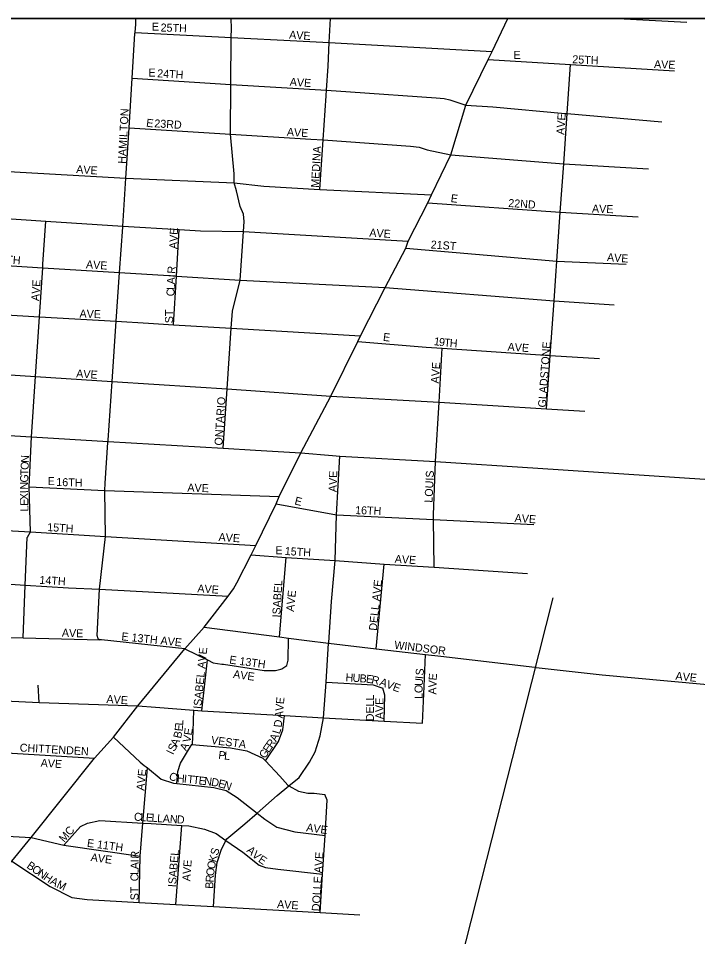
# Model space of a CAD drawing. Extents: x 0 to 34, y -6.2 to 22.
# Drawn here: x 7.668 to 8.471, y 20.104 to 21.19 of the extents above; entities that cross this region are included whole.
import ezdxf

# ---------------------------------------------------------------- set-up
doc = ezdxf.new("R2010")
doc.units = 0
for name, color, linetype in [('GM_X_City_Street', 7, 'Continuous'), ('GM_X_City_Street_Text', 7, 'Continuous'), ('GM_X_Corporation', 7, 'Continuous'), ('GM_X_Rail_Line', 7, 'Continuous'), ('GM_X_State_Route', 7, 'Continuous'), ('GM_X_Township', 7, 'Continuous'), ('SH_Data', 7, 'Continuous')]:
    doc.layers.add(name, color=color, linetype=linetype)

msp = doc.modelspace()

# ---------------------------------------------------------------- linework, layer by layer
at = {"layer": 'GM_X_City_Street'}
for points in [[(7.7742, 20.6887), (7.7743, 20.6898), (7.7744, 20.6915), (7.7792, 20.7608), (7.7841, 20.8319), (7.788, 20.8896), (7.7917, 20.9431), (7.7918, 20.9446), (7.7954, 21.0011), (7.7991, 21.0606), (7.8028, 21.1193), (7.8061, 21.1721), (7.8063, 21.1736), (7.8071, 21.1835), (7.8072, 21.1902)], [(7.9105, 20.6818), (7.9152, 20.7521), (7.92, 20.8236), (7.9214, 20.8438), (7.9306, 20.8806), (7.9343, 20.9383), (7.9351, 20.9498), (7.9346, 20.9585), (7.9306, 20.9676), (7.9262, 20.9863), (7.9233, 20.9957), (7.9233, 21.0062), (7.919, 21.0533), (7.9195, 21.1121), (7.92, 21.1677), (7.9201, 21.1781), (7.9198, 21.1902)], [(8.0321, 21.099), (8.0326, 21.1051), (8.0345, 21.1336), (8.0359, 21.1615), (8.0374, 21.1902)], [(8.3769, 21.1902), (8.4586, 21.1855)], [(7.8063, 21.1736), (7.92, 21.1677), (7.9973, 21.1636), (8.0359, 21.1615), (8.2283, 21.1508)], [(8.2237, 21.1414), (8.3212, 21.1355), (8.4438, 21.128)], [(8.2927, 20.7283), (8.2971, 20.7916), (8.3017, 20.8561), (8.3038, 20.8856), (8.305, 20.9031), (8.309, 20.9608), (8.313, 21.0183), (8.3171, 21.0775), (8.3212, 21.1355)], [(7.8028, 21.1193), (7.9195, 21.1121), (8.0326, 21.1051), (8.061, 21.1033), (8.1621, 21.0963), (8.1715, 21.0955), (8.1783, 21.0937), (8.1892, 21.0903), (8.1973, 21.0877), (8.2292, 21.0856), (8.3147, 21.0777), (8.3171, 21.0775), (8.429, 21.0678)], [(8.0246, 20.9876), (8.0286, 21.0464), (8.0321, 21.0984), (8.0321, 21.099)], [(7.7991, 21.0606), (7.919, 21.0533), (8.014, 21.0475), (8.0286, 21.0464), (8.1318, 21.039), (8.1423, 21.0378), (8.1517, 21.0348), (8.1795, 21.0287), (8.313, 21.0183), (8.4131, 21.0122)], [(7.5578, 21.011), (7.5625, 21.0135), (7.5682, 21.0144), (7.6217, 21.0112), (7.7954, 21.0011), (7.9233, 20.9957), (7.9583, 20.9916), (8.0246, 20.9876), (8.1566, 20.9814)], [(8.1525, 20.9721), (8.309, 20.9608), (8.4012, 20.9554)], [(7.5547, 20.9598), (7.6189, 20.9557), (7.7009, 20.9505), (7.7918, 20.9446), (7.8584, 20.9404), (7.8837, 20.9388), (7.9343, 20.9383), (8.1293, 20.9267)], [(7.6971, 20.8952), (7.6974, 20.8994), (7.7009, 20.9505)], [(7.8517, 20.8278), (7.8551, 20.8854), (7.8584, 20.9404)], [(8.1265, 20.9182), (8.305, 20.9031), (8.387, 20.8994)], [(7.5578, 20.9039), (7.6165, 20.9002), (7.6971, 20.8952), (7.788, 20.8896), (7.846, 20.886), (7.8551, 20.8854), (7.9306, 20.8806), (8.1019, 20.8718), (8.3017, 20.8561), (8.3726, 20.8513)], [(7.679, 20.5766), (7.6825, 20.583), (7.6812, 20.6361), (7.6837, 20.6951), (7.6885, 20.7666), (7.6932, 20.8373), (7.6971, 20.8952)], [(7.5624, 20.8452), (7.6139, 20.8421), (7.6932, 20.8373), (7.7841, 20.8319), (7.8221, 20.8296), (7.8517, 20.8278), (7.92, 20.8236), (8.0729, 20.8148)], [(8.0697, 20.8079), (8.1505, 20.8013), (8.1695, 20.8), (8.2971, 20.7916), (8.3554, 20.7878)], [(8.159, 20.5975), (8.1592, 20.603), (8.1616, 20.6661), (8.1657, 20.7363), (8.1695, 20.8)], [(7.5672, 20.7744), (7.6885, 20.7666), (7.7792, 20.7608), (7.8777, 20.7544), (7.9152, 20.7521), (8.0375, 20.7433), (8.1657, 20.7363), (8.2927, 20.7283), (8.3381, 20.7255)], [(7.6049, 20.7005), (7.6098, 20.6996), (7.6248, 20.6987), (7.6837, 20.6951), (7.7743, 20.6898), (7.9105, 20.6818), (7.9486, 20.6796)], [(7.7667, 20.4551), (7.7647, 20.4553), (7.7632, 20.4561), (7.7625, 20.4565), (7.7614, 20.4603), (7.7643, 20.515), (7.7714, 20.5775), (7.7704, 20.6317), (7.7709, 20.6404), (7.7742, 20.6887)], [(7.9486, 20.6796), (8.0022, 20.6765), (8.0397, 20.6733)], [(8.0352, 20.452), (8.0383, 20.5005), (8.0428, 20.5488), (8.0443, 20.6031), (8.0483, 20.6725)], [(8.0397, 20.6733), (8.0483, 20.6725), (8.1616, 20.6661), (8.2825, 20.6581)], [(8.2825, 20.6581), (8.5455, 20.6407), (8.6, 20.634), (8.6625, 20.6299), (8.7252, 20.6249), (8.7866, 20.6204), (8.8412, 20.6135), (8.9134, 20.612), (8.9666, 20.6077), (8.9733, 20.6073)], [(7.6812, 20.6361), (7.7704, 20.6317), (7.9766, 20.6245)], [(7.9732, 20.6161), (8.0443, 20.6031), (8.159, 20.5975), (8.2778, 20.5917)], [(8.1598, 20.5411), (8.159, 20.5975)], [(7.6256, 20.586), (7.6825, 20.583), (7.7714, 20.5775), (7.9489, 20.5667)], [(7.674, 20.4574), (7.6765, 20.52), (7.6788, 20.5762), (7.679, 20.5766)], [(7.9434, 20.5555), (7.9848, 20.5526), (8.0428, 20.5488), (8.1009, 20.5448), (8.1598, 20.5411), (8.2701, 20.5335)], [(7.977, 20.4589), (7.9848, 20.5526)], [(8.0912, 20.4446), (8.1009, 20.5448)], [(7.611, 20.5242), (7.6765, 20.52), (7.7276, 20.5168), (7.7643, 20.515), (7.9165, 20.507)], [(7.5385, 20.4621), (7.5505, 20.4602), (7.5959, 20.4592), (7.6045, 20.459), (7.674, 20.4574), (7.7647, 20.4553)], [(7.8881, 20.4703), (7.977, 20.4589), (7.9877, 20.4573), (8.0093, 20.4542), (8.0351, 20.4512), (8.0912, 20.4446), (8.1498, 20.4378), (8.1676, 20.4357), (8.2787, 20.4228)], [(7.865, 20.4446), (7.7667, 20.4551)], [(7.8988, 20.1397), (7.9014, 20.177), (7.9033, 20.1918), (7.9079, 20.2065), (7.9137, 20.2179), (7.9147, 20.2199), (7.9361, 20.2376), (7.9505, 20.2502), (7.9742, 20.271), (7.9882, 20.2825), (8.0002, 20.2923), (8.0124, 20.3106), (8.0192, 20.3226), (8.0251, 20.3417), (8.0291, 20.363), (8.0322, 20.4049), (8.0351, 20.4512), (8.0352, 20.452), (8.0352, 20.452)], [(7.9797, 20.421), (7.9857, 20.4249), (7.9874, 20.4313), (7.9877, 20.4573)], [(7.865, 20.4446), (7.8917, 20.4317), (7.8987, 20.4281), (7.9087, 20.4265), (7.9109, 20.4262)], [(7.8853, 20.3713), (7.8917, 20.4317)], [(8.146, 20.3566), (8.148, 20.3998), (8.1498, 20.4378)], [(7.9109, 20.4262), (7.9587, 20.4188), (7.9723, 20.4188), (7.9787, 20.4206), (7.9796, 20.4209), (7.9797, 20.421)], [(8.2787, 20.4228), (8.2804, 20.4226), (8.3584, 20.4136), (8.5171, 20.3992)], [(7.6927, 20.3812), (7.6917, 20.4016)], [(8.0322, 20.4049), (8.0878, 20.4019), (8.0991, 20.3978)], [(8.1009, 20.359), (8.1015, 20.3897), (8.0991, 20.3978)], [(7.5372, 20.3923), (7.5496, 20.3911), (7.5953, 20.3869), (7.62, 20.3846), (7.6927, 20.3812), (7.8095, 20.377), (7.8303, 20.3754)], [(7.8303, 20.3754), (7.8759, 20.3718), (7.8853, 20.3713), (7.9829, 20.3656), (8.0291, 20.363), (8.1009, 20.359), (8.146, 20.3566)], [(7.8557, 20.2851), (7.8567, 20.2994), (7.86, 20.3092), (7.8696, 20.3252), (7.8734, 20.3314), (7.874, 20.3323), (7.8751, 20.3467), (7.8759, 20.3718)], [(7.9604, 20.3119), (7.976, 20.3348), (7.9809, 20.3487), (7.9829, 20.3656)], [(7.7809, 20.34), (7.8121, 20.3104), (7.8171, 20.3067)], [(7.8734, 20.3314), (7.9189, 20.3273), (7.9385, 20.3237), (7.9572, 20.3152), (7.9604, 20.3119), (7.9775, 20.2941), (7.987, 20.2832), (7.9882, 20.2825), (7.9993, 20.276), (8.0106, 20.2738), (8.0178, 20.274), (8.0307, 20.2721)], [(7.5947, 20.324), (7.648, 20.3218), (7.7582, 20.3153)], [(7.811, 20.1445), (7.8122, 20.1993), (7.8155, 20.2383), (7.8211, 20.3036)], [(7.8171, 20.3067), (7.8194, 20.305), (7.8211, 20.3036), (7.8371, 20.2905), (7.8518, 20.2855), (7.8557, 20.2851), (7.8994, 20.2804), (7.9141, 20.2769), (7.9271, 20.2686), (7.9505, 20.2502), (7.9597, 20.243), (7.9739, 20.2335), (7.9953, 20.2279), (8.0309, 20.2236)], [(8.0252, 20.1327), (8.028, 20.178), (8.0309, 20.2236), (8.0335, 20.2656), (8.0307, 20.2721)], [(7.0262, 20.2529), (7.0739, 20.2508), (7.1627, 20.2469), (7.2147, 20.245), (7.2579, 20.2435), (7.3116, 20.2416), (7.3693, 20.2396), (7.3718, 20.2395), (7.4115, 20.2379), (7.4632, 20.2358), (7.5007, 20.2343), (7.5328, 20.2314), (7.5542, 20.2296), (7.5864, 20.2268), (7.6479, 20.2232), (7.6835, 20.2215)], [(7.7221, 20.2125), (7.7419, 20.2343), (7.75, 20.2382), (7.7645, 20.2413), (7.8155, 20.2383), (7.8252, 20.2378)], [(7.8252, 20.2378), (7.8617, 20.2357), (7.8697, 20.2353), (7.8885, 20.2313), (7.902, 20.226), (7.9137, 20.2179), (7.9336, 20.2042), (7.9529, 20.1885), (7.9604, 20.186), (7.9751, 20.1841), (8.028, 20.178)], [(7.8545, 20.1421), (7.8617, 20.2357)], [(7.6835, 20.2215), (7.7221, 20.2125), (7.8122, 20.1993)], [(7.6606, 20.1934), (7.7058, 20.1636), (7.7316, 20.1503), (7.7497, 20.1479), (7.811, 20.1445), (7.8545, 20.1421), (7.8988, 20.1397), (8.0252, 20.1327), (8.0721, 20.1301)]]:
    msp.add_lwpolyline(points, dxfattribs=at)
at = {"layer": 'GM_X_Corporation'}
msp.add_lwpolyline([(5.4833, 14.3902), (9.0755, 14.3902), (9.0755, 21.1902), (4.181, 21.1902)], dxfattribs=at)
at = {"layer": 'GM_X_Rail_Line'}
msp.add_lwpolyline([(8.1767, 20.0174), (8.1914, 20.0742), (8.2588, 20.3396), (8.3007, 20.5048)], dxfattribs=at)
at = {"layer": 'GM_X_State_Route'}
for points in [[(8.0022, 20.6765), (8.0375, 20.7433), (8.0697, 20.8079), (8.0729, 20.8148), (8.1019, 20.8718), (8.1265, 20.9182), (8.1293, 20.9267), (8.1525, 20.9721), (8.1566, 20.9814), (8.1795, 21.0287), (8.1973, 21.0877), (8.2237, 21.1414), (8.2283, 21.1508), (8.2469, 21.1902)], [(7.5487, 20.0559), (7.5562, 20.065), (7.6299, 20.1615), (7.6606, 20.1934), (7.6835, 20.2215), (7.7582, 20.3153), (7.7809, 20.34), (7.8095, 20.377), (7.865, 20.4446), (7.8881, 20.4703), (7.9165, 20.507), (7.9227, 20.5156), (7.9267, 20.5227), (7.9434, 20.5555), (7.9489, 20.5667), (7.9732, 20.6161), (7.9766, 20.6245), (8.0022, 20.6765)]]:
    msp.add_lwpolyline(points, dxfattribs=at)
at = {"layer": 'GM_X_Township'}
msp.add_line((9.0029, 21.1902), (4.1671, 21.1902), dxfattribs=at)
at = {"layer": 'SH_Data'}
msp.add_lwpolyline([(9.0755, 21.1902), (9.0755, 14.3902), (2.2755, 14.3902), (2.2755, 21.1902)], close=True, dxfattribs=at)

# ---------------------------------------------------------------- texts
at = {"layer": 'GM_X_City_Street_Text'}
for s, rotation, p in [('E', 0, (7.8262, 21.1756)), ('25TH', 358.2109, (7.8363, 21.1747)), ('A', 355.0766, (7.9881, 21.1664)), ('V', 356.3898, (7.9966, 21.1657)), ('E', 356.7969, (8.005, 21.1651)), ('E', 0, (8.2537, 21.1422)), ('25TH', 357.2752, (8.323, 21.1372)), ('AVE', 358.0264, (8.4196, 21.1314)), ('E', 0, (7.8221, 21.1214)), ('24TH', 356.4254, (7.8322, 21.1206)), ('AVE', 356.0494, (7.9889, 21.1106)), ('HAMILTON', 86.9077, (7.7953, 21.018)), ('E', 352.8783, (7.819, 21.0622)), ('23RD', 356.5338, (7.8288, 21.0614)), ('AVE', 86.0494, (8.3136, 21.0522)), ('AVE', 356.0499, (7.9855, 21.0514)), ('MEDINA', 86.9313, (8.0236, 20.9897)), ('AVE', 356.0569, (7.7364, 21.0072)), ('E', 352.8783, (8.179, 20.973)), ('22ND', 356.1015, (8.2472, 20.9672)), ('AVE', 358.0261, (8.3463, 20.9606)), ('AVE', 87.9557, (7.8561, 20.9172)), ('AVE', 356.0569, (8.083, 20.9322)), ('21ST', 356.1879, (8.1555, 20.9181)), ('20TH', 355.9114, (7.6397, 20.9014)), ('AVE', 355.9166, (8.3639, 20.9031)), ('AVE', 356.0569, (7.748, 20.8947)), ('R', 85.795, (7.8538, 20.8879)), ('I', 86.7208, (7.8536, 20.8838)), ('AVE', 86.0569, (7.6928, 20.8556)), ('L', 87.978, (7.8531, 20.8688)), ('A', 87.8579, (7.8533, 20.8755)), ('C', 88.0083, (7.8528, 20.8613)), ('AVE', 358.0261, (7.7405, 20.8364)), ('ST', 90, (7.8511, 20.8296)), ('E', 352.8514, (8.099, 20.8089)), ('1', 351.4106, (8.159, 20.8039)), ('9', 352.8141, (8.165, 20.803)), ('T', 355.4209, (8.1713, 20.8022)), ('H', 356.0554, (8.178, 20.8016)), ('AVE', 356.0499, (8.2464, 20.7972)), ('GLADSTONE', 85.8676, (8.292, 20.7297)), ('AVE', 86.0569, (8.1653, 20.7581)), ('AVE', 356.0569, (7.7364, 20.7656)), ('ONTARIO', 86.3106, (7.9095, 20.6847)), ('N', 87.4639, (7.6807, 20.6643)), ('T', 87.4582, (7.68, 20.6494)), ('O', 87.4708, (7.6803, 20.656)), ('G', 87.5513, (7.6797, 20.641)), ('E', 0, (7.7029, 20.6381)), ('16TH', 358.2112, (7.713, 20.6372)), ('AVE', 88.0261, (8.0445, 20.6297)), ('LOUIS', 87.2035, (8.1578, 20.6172)), ('N', 89.2349, (7.6796, 20.6328)), ('AVE', 358.0261, (7.868, 20.6306)), ('I', 91.5742, (7.6797, 20.6287)), ('X', 91.6048, (7.6799, 20.6204)), ('E', 345.9702, (7.9942, 20.6155)), ('E', 91.5851, (7.6801, 20.6137)), ('L', 91.6124, (7.6803, 20.6071)), ('16TH', 358.2112, (8.0663, 20.6039)), ('AVE', 355.9088, (8.2547, 20.5947)), ('15TH', 356.419, (7.7022, 20.5839)), ('AVE', 356.0499, (7.9047, 20.5722)), ('E', 0, (7.9721, 20.5564)), ('15TH', 356.4258, (7.983, 20.5556)), ('AVE', 356.0574, (8.113, 20.5464)), ('14TH', 356.4254, (7.693, 20.5214)), ('AVE', 356.0569, (7.8797, 20.5114)), ('ISABEL', 86.4939, (7.9778, 20.4814)), ('DELL AVE', 84.0353, (8.092, 20.4656)), ('AVE', 84.0895, (7.994, 20.4881)), ('AVE', 358.0264, (7.7196, 20.4589)), ('E 13TH AVE', 353.9911, (7.7898, 20.4547)), ('WINDSOR', 352.9843, (8.1123, 20.4447)), ('ISABEL AVE', 84.3597, (7.8845, 20.3731)), ('E 13TH', 352.2339, (7.9173, 20.4272)), ('AVE', 352.1434, (7.9218, 20.4102)), ('S', 85.2137, (8.1472, 20.4127)), ('H', 355.8174, (8.0548, 20.4063)), ('U', 355.8174, (8.0631, 20.4057)), ('B', 355.8174, (8.0714, 20.4051)), ('E', 353.1183, (8.0788, 20.4046)), ('R', 347.7201, (8.0851, 20.4038)), ('A', 339.6228, (8.0945, 20.4016)), ('V', 339.6228, (8.1023, 20.3987)), ('U', 85.9315, (8.1463, 20.4003)), ('I', 85.2291, (8.1469, 20.4085)), ('V', 87.6168, (8.1625, 20.3987)), ('E', 86.8565, (8.1628, 20.407)), ('AVE', 354.0969, (8.4448, 20.408)), ('E', 339.6228, (8.1101, 20.3958)), ('O', 89.0382, (8.1461, 20.3921)), ('A', 89.3442, (8.1624, 20.3904)), ('AVE', 356.0499, (7.7722, 20.3806)), ('E', 84.8031, (7.9822, 20.3788)), ('DELL', 90, (8.0886, 20.3588)), ('AVE', 90, (8.0999, 20.3613)), ('L', 89.8907, (8.1461, 20.3854)), ('V', 84.8135, (7.9814, 20.3705)), ('A', 84.8135, (7.9807, 20.3622)), ('E', 84.7966, (7.8624, 20.3467)), ('L', 87.0235, (7.8631, 20.3537)), ('D', 83.842, (7.9795, 20.3512)), ('B', 76.4133, (7.8604, 20.3379)), ('V', 78.2892, (7.8715, 20.3331)), ('E', 81.463, (7.8733, 20.3418)), ('A', 64.4931, (7.9731, 20.334)), ('L', 73.8241, (7.9773, 20.3431)), ('CHITTENDEN', 356.7473, (7.6697, 20.3231)), ('S', 63.5816, (7.8529, 20.3223)), ('A', 63.5913, (7.8559, 20.3283)), ('A', 62.9072, (7.8668, 20.323)), ('VESTA', 352.4025, (7.8957, 20.3322)), ('E', 55.984, (7.9644, 20.3209)), ('R', 55.9972, (7.9682, 20.3264)), ('I', 63.5913, (7.8511, 20.3186)), ('P', 352.492, (7.9043, 20.3146)), ('L', 354.0912, (7.9112, 20.3137)), ('G', 55.9947, (7.9598, 20.314)), ('AVE', 356.0569, (7.6944, 20.3051)), ('AVE', 84.0969, (7.817, 20.2765)), ('C', 338.5684, (7.8454, 20.2904)), ('H', 355.6123, (7.8554, 20.2869)), ('I', 353.515, (7.8636, 20.2863)), ('T', 353.4849, (7.8677, 20.2858)), ('T', 353.4956, (7.8743, 20.2851)), ('E', 353.4849, (7.881, 20.2843)), ('N', 353.4914, (7.8876, 20.2836)), ('D', 349.8046, (7.8957, 20.2827)), ('E', 346.0963, (7.9038, 20.2812)), ('N', 340.3623, (7.91, 20.2797)), ('C', 356.3797, (7.8047, 20.2414)), ('L', 356.364, (7.8122, 20.2409)), ('E', 356.3543, (7.8188, 20.2405)), ('L', 356.3685, (7.8255, 20.2401)), ('L', 356.3791, (7.8321, 20.2396)), ('A', 356.3691, (7.8388, 20.2392)), ('N', 356.3673, (7.8471, 20.2387)), ('D', 356.3673, (7.8554, 20.2382)), ('MC', 48.581, (7.7224, 20.215)), ('AVE', 351.8743, (8.0082, 20.2289)), ('E 11TH', 352.2346, (7.749, 20.2105)), ('AVE', 352.1434, (7.7534, 20.1936)), ('R', 85.6981, (7.8104, 20.1961)), ('ISABEL', 85.3312, (7.8545, 20.1623)), ('K', 75.3754, (7.902, 20.1915)), ('S', 73.6567, (7.904, 20.1995)), ('A', 318.5879, (7.9374, 20.2051)), ('V', 318.6208, (7.9437, 20.1996)), ('DOLLE AVE', 86.3314, (8.0245, 20.1339)), ('B', 325.2926, (7.6773, 20.1861)), ('I', 89.6941, (7.8104, 20.1921)), ('A', 89.7112, (7.8104, 20.1838)), ('AVE', 86.0569, (7.8715, 20.1694)), ('O', 79.7147, (7.9005, 20.1834)), ('E', 326.5025, (7.9511, 20.1932)), ('O', 325.2855, (7.6834, 20.1818)), ('N', 325.2912, (7.6903, 20.1771)), ('H', 325.2912, (7.6971, 20.1723)), ('L', 89.7191, (7.8103, 20.1771)), ('O', 82.4169, (7.8994, 20.1753)), ('A', 331.0281, (7.7049, 20.167)), ('M', 334.6179, (7.7127, 20.1627)), ('C', 89.7085, (7.8103, 20.1696)), ('B', 87.0357, (7.8986, 20.1605)), ('R', 86.6464, (7.899, 20.168)), ('ST', 90, (7.8103, 20.1471)), ('AVE', 356.0499, (7.9739, 20.1381))]:
    msp.add_text(s, height=0.00947, rotation=rotation, dxfattribs=at).set_placement(p)

doc.saveas('drawing.dxf')
